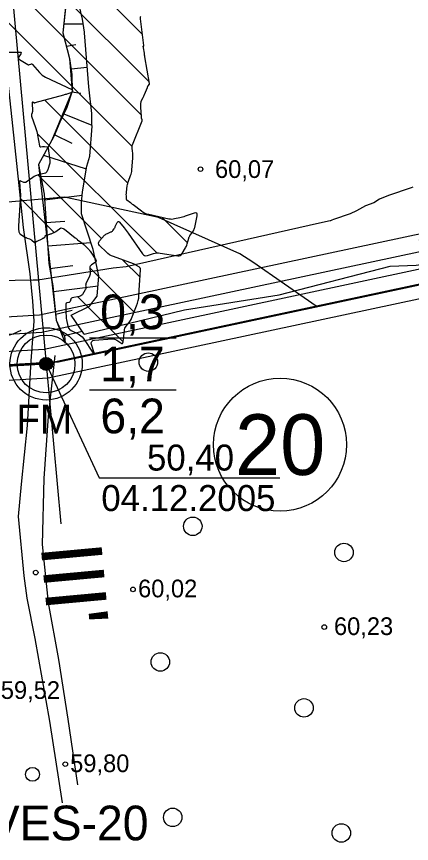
# Model space of a CAD drawing. Extents: x 532503 to 539665, y 6557663 to 6561526.
# Drawn here: x 534729.4 to 534784.1, y 6559418.8 to 6559533.2 of the extents above; entities that cross this region are included whole.
import ezdxf

# ---------------------------------------------------------------- set-up
doc = ezdxf.new("R2010")
doc.units = 0
for name, color, linetype in [('GEOLPUNKT', 7, 'Continuous'), ('HALJASTUS', 7, 'Continuous'), ('HORISONTAAL-EH2000', 7, 'Continuous'), ('illumineerimisjooned', 7, 'Continuous'), ('Kaevandatud ala', 7, 'Continuous'), ('kataster', 7, 'Continuous'), ('KORGUS-EH2000', 7, 'Continuous'), ('Lamami horisontaal_EH2000', 7, 'Continuous'), ('Lõige', 7, 'Continuous'), ('PIIR', 7, 'Continuous'), ('PIIR_me', 7, 'Continuous'), ('Plokid', 7, 'Continuous'), ('Proovid', 7, 'Continuous'), ('RELJEEF', 7, 'Continuous'), ('TEE', 7, 'Continuous'), ('TM_aktiivne', 7, 'Continuous'), ('Veetase', 7, 'Continuous')]:
    doc.layers.add(name, color=color, linetype=linetype)

# ---------------------------------------------------------------- blocks, each defined once
blk = doc.blocks.new('METS')
at = {"layer": 'HALJASTUS'}
blk.add_circle((0, 0), 0.8, dxfattribs=at)
blk = doc.blocks.new('LONOOR')
at = {"layer": 'HALJASTUS'}
blk.add_circle((0, 0), 0.6, dxfattribs=at)

msp = doc.modelspace()

# ---------------------------------------------------------------- linework, layer by layer
at = {"layer": 'GEOLPUNKT'}
for p, q in [((534739.5, 6559488.74), (534751.5, 6559488.74)), ((534739.5, 6559481.54), (534751.5, 6559481.54))]:
    msp.add_line(p, q, dxfattribs=at)
for radius in [5, 4, 0.9, 0.801, 0.7, 0.6, 0.5, 0.4, 0.3, 0.2, 0.1]:
    msp.add_circle((534733.5, 6559485.14), radius, dxfattribs=at)
at = {"layer": 'HORISONTAAL-EH2000'}
msp.add_lwpolyline([(534665.89, 6559465.57), (534680.27, 6559469.25), (534695.13, 6559472.57), (534702.12, 6559475.18), (534705.46, 6559476.87), (534710.19, 6559479.95), (534716.29, 6559484.76), (534719.55, 6559486.64), (534728.96, 6559489.29), (534730.07, 6559489.8)], dxfattribs=at)
at = {"layer": 'illumineerimisjooned'}
msp.add_lwpolyline([(534195.15, 6559981.19), (534198.98, 6559981.55), (535160.12, 6560071.77), (535418.53, 6559993.82), (535458.87, 6559929.25), (535494.63, 6559867.7), (535482.6, 6559826), (535251.74, 6559649.68), (535250.36, 6559648.53), (535180.45, 6559687.33), (534941.15, 6559814.59), (534876.93, 6559774.72), (534959.62, 6559531.32), (534733.77, 6559483.15), (534375.91, 6559461.87), (534195.51, 6559444.47)], dxfattribs=at)
msp.add_lwpolyline([(534967.67, 6560049.69), (534974.15, 6559828.08), (535058.69, 6559883.05), (535223.5, 6560002.45), (535218.56, 6560049.92), (535415.93, 6559990.42), (535455.45, 6559927.19), (535490.31, 6559867.16), (535479.12, 6559828.38), (535249.57, 6559653.05), (535182.36, 6559690.84), (534940.99, 6559819.22), (534872.14, 6559776.44), (534954.37, 6559534.34), (534950.91, 6559533.67), (534733.22, 6559487.12), (534375.58, 6559465.86), (534199.95, 6559448.92), (533951.79, 6559660.13), (534200.21, 6559977.65), (534931.63, 6560046.31)], close=True, dxfattribs=at)
at = {"layer": 'Kaevandatud ala'}
for p, q in [((534725.57, 6559552.02), (534746.84, 6559530.75)), ((534724.38, 6559547.55), (534747.78, 6559524.16)), ((534723.24, 6559543.04), (534746.68, 6559519.6)), ((534723.34, 6559537.28), (534745.4, 6559515.22)), ((534733.33, 6559521.64), (534744.81, 6559510.15)), ((534732.27, 6559517.03), (534748.81, 6559500.5)), ((534732.36, 6559511.29), (534741.17, 6559502.48)), ((534729.91, 6559508.08), (534734.64, 6559503.35)), ((534749.56, 6559505.4), (534753.07, 6559501.9)), ((534744.14, 6559499.51), (534746.52, 6559497.13)), ((534739.56, 6559498.43), (534745.68, 6559492.31)), ((534737.91, 6559494.43), (534744.16, 6559488.18)), ((534736.64, 6559490.04), (534736.8, 6559489.88)), ((534739.95, 6559486.73), (534740.13, 6559486.55)), ((534740.08, 6559486.54), (534740.21, 6559486.57))]:
    msp.add_line(p, q, dxfattribs=at)
for points in [[(534740.21, 6559486.57), (534740.17, 6559486.68), (534739.8, 6559487.82), (534739.76, 6559488.07), (534739.81, 6559488.25), (534739.96, 6559488.37), (534740.21, 6559488.43), (534742.65, 6559488.62), (534742.82, 6559488.62), (534742.98, 6559488.59), (534743.13, 6559488.54), (534743.28, 6559488.45), (534743.84, 6559488.05), (534743.97, 6559487.98), (534744.06, 6559487.98), (534744.13, 6559488.05), (534744.16, 6559488.19), (534744.34, 6559489.76), (534744.37, 6559489.92), (534744.42, 6559490.08), (534744.5, 6559490.22), (534744.59, 6559490.35), (534745.01, 6559490.87), (534745.11, 6559491.01), (534745.2, 6559491.15), (534745.27, 6559491.29), (534745.34, 6559491.44), (534746.03, 6559493.2), (534746.15, 6559493.54), (534746.25, 6559493.9), (534746.32, 6559494.26), (534746.35, 6559494.62), (534746.59, 6559498.18), (534746.58, 6559498.29), (534746.55, 6559498.38), (534746.49, 6559498.46), (534746.41, 6559498.53), (534746.01, 6559498.78), (534745.91, 6559498.84), (534745.81, 6559498.89), (534745.71, 6559498.94), (534745.6, 6559498.98), (534742.81, 6559499.99), (534742.54, 6559500.1), (534742.29, 6559500.24), (534742.06, 6559500.41), (534741.84, 6559500.6), (534740.9, 6559501.54), (534740.79, 6559501.69), (534740.75, 6559501.85), (534740.78, 6559502), (534740.89, 6559502.16), (534741.6, 6559502.95), (534741.69, 6559503.03), (534741.78, 6559503.1), (534741.87, 6559503.16), (534741.98, 6559503.21), (534742.48, 6559503.4), (534742.56, 6559503.43), (534742.62, 6559503.47), (534742.68, 6559503.53), (534742.73, 6559503.59), (534742.91, 6559503.86), (534742.95, 6559503.92), (534743, 6559503.99), (534743.04, 6559504.06), (534743.07, 6559504.14), (534743.35, 6559504.72), (534743.42, 6559504.81), (534743.49, 6559504.85), (534743.56, 6559504.83), (534743.65, 6559504.75), (534744.32, 6559503.96), (534744.46, 6559503.79), (534744.59, 6559503.62), (534744.73, 6559503.44), (534744.85, 6559503.26), (534746.83, 6559500.39), (534746.97, 6559500.23), (534747.13, 6559500.14), (534747.31, 6559500.11), (534747.52, 6559500.15), (534748.39, 6559500.42), (534748.61, 6559500.47), (534748.83, 6559500.5), (534749.05, 6559500.5), (534749.27, 6559500.48), (534751.72, 6559500.12), (534751.9, 6559500.12), (534752.07, 6559500.16), (534752.21, 6559500.26), (534752.32, 6559500.41), (534752.78, 6559501.19), (534752.86, 6559501.32), (534752.92, 6559501.46), (534752.98, 6559501.6), (534753.02, 6559501.74), (534753.25, 6559502.53), (534753.27, 6559502.57), (534753.28, 6559502.62), (534753.3, 6559502.66), (534753.32, 6559502.7), (534753.39, 6559502.87), (534753.41, 6559502.91), (534753.43, 6559502.95), (534753.45, 6559502.99), (534753.48, 6559503.03), (534753.89, 6559503.58), (534753.96, 6559503.69), (534754.02, 6559503.8), (534754.06, 6559503.92), (534754.09, 6559504.04), (534754.4, 6559505.64), (534754.42, 6559505.87), (534754.35, 6559506.01), (534754.21, 6559506.06), (534753.98, 6559506.01), (534752.75, 6559505.57), (534752.57, 6559505.51), (534752.38, 6559505.45), (534752.2, 6559505.4), (534752.01, 6559505.36), (534751.26, 6559505.2), (534751.07, 6559505.16), (534750.89, 6559505.15), (534750.7, 6559505.16), (534750.51, 6559505.19), (534747.71, 6559505.8), (534747.44, 6559505.88), (534747.18, 6559505.98), (534746.94, 6559506.11), (534746.71, 6559506.26), (534745.54, 6559507.15), (534745.45, 6559507.22), (534745.36, 6559507.3), (534745.26, 6559507.37), (534745.17, 6559507.44), (534744.69, 6559507.82), (534744.66, 6559507.86), (534744.64, 6559507.89), (534744.62, 6559507.93), (534744.62, 6559507.97), (534744.61, 6559508.16), (534744.61, 6559508.2), (534744.61, 6559508.25), (534744.61, 6559508.29), (534744.61, 6559508.34), (534744.6, 6559508.65), (534744.61, 6559508.72), (534744.61, 6559508.79), (534744.61, 6559508.86), (534744.62, 6559508.92), (534744.74, 6559509.8), (534744.77, 6559509.96), (534744.81, 6559510.13), (534744.85, 6559510.29), (534744.91, 6559510.45), (534745.2, 6559511.22), (534745.27, 6559511.41), (534745.32, 6559511.59), (534745.35, 6559511.78), (534745.37, 6559511.97), (534745.51, 6559513.67), (534745.51, 6559513.79), (534745.52, 6559513.91), (534745.51, 6559514.03), (534745.5, 6559514.15), (534745.44, 6559514.74), (534745.43, 6559514.8), (534745.43, 6559514.86), (534745.42, 6559514.92), (534745.42, 6559514.98), (534745.4, 6559515.22), (534745.4, 6559515.28), (534745.41, 6559515.34), (534745.42, 6559515.4), (534745.44, 6559515.45), (534746.82, 6559518.79), (534746.82, 6559518.8), (534746.82, 6559518.81), (534746.82, 6559518.82), (534746.82, 6559518.83), (534746.8, 6559518.88), (534746.79, 6559518.89), (534746.79, 6559518.9), (534746.79, 6559518.92), (534746.78, 6559518.93), (534746.75, 6559519.05), (534746.74, 6559519.07), (534746.74, 6559519.1), (534746.73, 6559519.12), (534746.73, 6559519.14), (534746.71, 6559519.28), (534746.7, 6559519.32), (534746.7, 6559519.35), (534746.7, 6559519.38), (534746.69, 6559519.41), (534746.65, 6559519.94), (534746.65, 6559520.04), (534746.64, 6559520.14), (534746.64, 6559520.24), (534746.63, 6559520.34), (534746.62, 6559521.14), (534746.63, 6559521.26), (534746.65, 6559521.37), (534746.68, 6559521.48), (534746.72, 6559521.58), (534746.93, 6559522), (534746.98, 6559522.1), (534747.03, 6559522.21), (534747.08, 6559522.32), (534747.12, 6559522.42), (534747.52, 6559523.42), (534747.53, 6559523.44), (534747.54, 6559523.46), (534747.55, 6559523.47), (534747.56, 6559523.49), (534747.6, 6559523.56), (534747.61, 6559523.57), (534747.62, 6559523.59), (534747.63, 6559523.6), (534747.64, 6559523.62), (534747.78, 6559523.8), (534747.8, 6559523.83), (534747.81, 6559523.87), (534747.82, 6559523.91), (534747.81, 6559523.95), (534747.18, 6559527.62), (534747.16, 6559527.75), (534747.14, 6559527.87), (534747.12, 6559528), (534747.1, 6559528.13), (534747, 6559528.88), (534747, 6559528.89), (534747, 6559528.9), (534747, 6559528.9), (534747, 6559528.91), (534746.98, 6559528.94), (534746.97, 6559528.95), (534746.92, 6559529.06), (534746.91, 6559529.08), (534746.91, 6559529.09), (534746.92, 6559529.1), (534746.94, 6559529.11), (534747.01, 6559529.13), (534747.03, 6559529.14), (534747.04, 6559529.15), (534747.05, 6559529.17), (534747.05, 6559529.19), (534746.56, 6559532.92), (534746.56, 6559533), (534746.57, 6559533.08), (534746.59, 6559533.16), (534746.63, 6559533.23)], [(534727.82, 6559528.29), (534729.89, 6559528.29), (534730, 6559528.27), (534730.05, 6559528.23), (534730.06, 6559528.16), (534730.01, 6559528.07), (534729.73, 6559527.64), (534729.68, 6559527.53), (534729.68, 6559527.44), (534729.72, 6559527.36), (534729.81, 6559527.29), (534730.96, 6559526.58), (534731.02, 6559526.55), (534731.07, 6559526.54), (534731.13, 6559526.54), (534731.18, 6559526.56), (534731.41, 6559526.64), (534731.47, 6559526.65), (534731.52, 6559526.65), (534731.56, 6559526.63), (534731.61, 6559526.59), (534732.57, 6559525.46), (534732.76, 6559525.27), (534732.96, 6559525.1), (534733.17, 6559524.95), (534733.41, 6559524.82), (534737.05, 6559523.11), (534737.07, 6559523.1), (534737.08, 6559523.09), (534737.09, 6559523.08), (534737.09, 6559523.07), (534737.13, 6559523), (534737.13, 6559523), (534737.13, 6559522.99), (534737.14, 6559522.98), (534737.14, 6559522.97), (534737.14, 6559522.96), (534737.14, 6559522.92), (534737.14, 6559522.91), (534737.14, 6559522.9), (534737.14, 6559522.89), (534737.14, 6559522.88), (534737.12, 6559522.76), (534737.11, 6559522.74), (534737.1, 6559522.72), (534737.09, 6559522.71), (534737.07, 6559522.7), (534736.38, 6559522.49), (534736.26, 6559522.45), (534736.13, 6559522.42), (534736.01, 6559522.38), (534735.89, 6559522.35), (534731.96, 6559521.26), (534731.92, 6559521.25), (534731.88, 6559521.25), (534731.84, 6559521.26), (534731.81, 6559521.28), (534731.67, 6559521.36), (534731.63, 6559521.37), (534731.61, 6559521.37), (534731.6, 6559521.35), (534731.59, 6559521.32), (534731.6, 6559520.09), (534731.6, 6559520.03), (534731.59, 6559519.97), (534731.58, 6559519.92), (534731.57, 6559519.87), (534731.49, 6559519.65), (534731.48, 6559519.6), (534731.47, 6559519.54), (534731.48, 6559519.49), (534731.49, 6559519.43), (534732.04, 6559517.85), (534732.13, 6559517.59), (534732.2, 6559517.33), (534732.27, 6559517.07), (534732.32, 6559516.8), (534732.58, 6559515.32), (534732.6, 6559515.26), (534732.64, 6559515.22), (534732.68, 6559515.19), (534732.75, 6559515.19), (534733.02, 6559515.21), (534733.09, 6559515.21), (534733.16, 6559515.21), (534733.23, 6559515.21), (534733.3, 6559515.21), (534733.62, 6559515.18), (534733.69, 6559515.17), (534733.74, 6559515.14), (534733.77, 6559515.09), (534733.79, 6559515.02), (534734.01, 6559513.3), (534734.02, 6559513.17), (534734.01, 6559513.05), (534734, 6559512.93), (534733.97, 6559512.8), (534733.8, 6559512.19), (534733.79, 6559512.13), (534733.76, 6559512.07), (534733.74, 6559512.01), (534733.71, 6559511.95), (534733.6, 6559511.71), (534733.57, 6559511.66), (534733.53, 6559511.61), (534733.48, 6559511.58), (534733.42, 6559511.56), (534732.38, 6559511.29), (534732.19, 6559511.24), (534732.01, 6559511.16), (534731.83, 6559511.07), (534731.67, 6559510.96), (534730.76, 6559510.31), (534730.68, 6559510.26), (534730.59, 6559510.24), (534730.49, 6559510.24), (534730.4, 6559510.27), (534730.02, 6559510.45), (534729.93, 6559510.48), (534729.88, 6559510.47), (534729.84, 6559510.42), (534729.84, 6559510.33), (534729.91, 6559509.03), (534729.92, 6559508.99), (534729.92, 6559508.95), (534729.92, 6559508.91), (534729.92, 6559508.87), (534729.94, 6559508.71), (534729.94, 6559508.67), (534729.94, 6559508.63), (534729.94, 6559508.59), (534729.94, 6559508.55), (534729.66, 6559504.23), (534729.66, 6559504.13), (534729.66, 6559504.03), (534729.66, 6559503.93), (534729.68, 6559503.82), (534729.73, 6559503.42), (534729.76, 6559503.32), (534729.8, 6559503.24), (534729.86, 6559503.16), (534729.94, 6559503.1), (534730.57, 6559502.7), (534730.64, 6559502.66), (534730.72, 6559502.62), (534730.8, 6559502.58), (534730.88, 6559502.55), (534731.22, 6559502.44), (534731.3, 6559502.41), (534731.37, 6559502.37), (534731.45, 6559502.32), (534731.52, 6559502.27), (534731.9, 6559501.96), (534731.93, 6559501.94), (534731.96, 6559501.93), (534731.98, 6559501.94), (534732.01, 6559501.96), (534732.13, 6559502.06), (534732.16, 6559502.09), (534732.19, 6559502.11), (534732.22, 6559502.13), (534732.25, 6559502.15), (534732.94, 6559502.46), (534732.98, 6559502.48), (534733.02, 6559502.51), (534733.06, 6559502.53), (534733.1, 6559502.55), (534733.33, 6559502.7), (534733.34, 6559502.71), (534733.34, 6559502.71), (534733.35, 6559502.72), (534733.36, 6559502.72), (534733.36, 6559502.73), (534733.37, 6559502.74), (534733.38, 6559502.75), (534733.38, 6559502.76), (534733.38, 6559502.77), (534733.4, 6559502.89), (534733.41, 6559502.91), (534733.42, 6559502.92), (534733.43, 6559502.94), (534733.45, 6559502.94), (534733.88, 6559503.06), (534733.95, 6559503.08), (534734.03, 6559503.1), (534734.1, 6559503.13), (534734.18, 6559503.16), (534734.55, 6559503.31), (534734.63, 6559503.35), (534734.72, 6559503.39), (534734.8, 6559503.44), (534734.87, 6559503.49), (534735.55, 6559503.99), (534735.55, 6559503.99), (534735.55, 6559503.99), (534735.56, 6559503.99), (534735.56, 6559503.99), (534735.86, 6559503.88), (534735.91, 6559503.86), (534735.95, 6559503.84), (534735.99, 6559503.81), (534736.03, 6559503.79), (534737.51, 6559502.6), (534737.6, 6559502.53), (534737.69, 6559502.46), (534737.78, 6559502.39), (534737.87, 6559502.32), (534738.31, 6559501.98), (534738.35, 6559501.95), (534738.4, 6559501.91), (534738.44, 6559501.88), (534738.48, 6559501.85), (534738.66, 6559501.72), (534738.7, 6559501.68), (534738.74, 6559501.65), (534738.78, 6559501.61), (534738.82, 6559501.57), (534739.28, 6559501.12), (534739.36, 6559501.03), (534739.44, 6559500.94), (534739.52, 6559500.84), (534739.59, 6559500.74), (534740.37, 6559499.57), (534740.43, 6559499.45), (534740.43, 6559499.35), (534740.39, 6559499.25), (534740.29, 6559499.17), (534739.79, 6559498.87), (534739.68, 6559498.78), (534739.6, 6559498.68), (534739.57, 6559498.56), (534739.56, 6559498.42), (534739.62, 6559497.84), (534739.62, 6559497.7), (534739.6, 6559497.56), (534739.57, 6559497.42), (534739.52, 6559497.29), (534739.02, 6559496.23), (534739, 6559496.16), (534738.98, 6559496.09), (534738.97, 6559496.02), (534738.98, 6559495.95), (534739, 6559495.66), (534739, 6559495.59), (534738.99, 6559495.52), (534738.96, 6559495.45), (534738.93, 6559495.39), (534738.52, 6559494.77), (534738.44, 6559494.65), (534738.33, 6559494.56), (534738.21, 6559494.5), (534738.07, 6559494.46), (534737.1, 6559494.27), (534737.03, 6559494.25), (534736.98, 6559494.21), (534736.94, 6559494.16), (534736.91, 6559494.09), (534736.82, 6559493.79), (534736.79, 6559493.73), (534736.75, 6559493.68), (534736.71, 6559493.65), (534736.64, 6559493.63), (534736.38, 6559493.58), (534736.32, 6559493.56), (534736.28, 6559493.53), (534736.25, 6559493.48), (534736.25, 6559493.42), (534736.25, 6559492.09), (534736.26, 6559491.87), (534736.27, 6559491.66), (534736.3, 6559491.45), (534736.33, 6559491.23), (534736.49, 6559490.39), (534736.55, 6559490.19), (534736.65, 6559490.03), (534736.78, 6559489.89), (534736.96, 6559489.78), (534737.93, 6559489.31), (534738.14, 6559489.19), (534738.33, 6559489.04), (534738.51, 6559488.87), (534738.66, 6559488.67), (534740.03, 6559486.61), (534740.08, 6559486.54)]]:
    msp.add_lwpolyline(points, dxfattribs=at)
at = {"layer": 'kataster'}
msp.add_lwpolyline([(533947.7, 6559658.95), (533949.2, 6559955.8), (534198.28, 6559979.48), (535159.89, 6560069.73), (535417.31, 6559992.13), (535457.22, 6559928.24), (535504.86, 6559846.09), (535250.3, 6559650.84), (535181.52, 6559689.04), (534941.15, 6559817.08), (534874.65, 6559775.26), (534957.01, 6559532.73), (534735.22, 6559485.45), (534375.71, 6559463.85), (534199.28, 6559446.9), (534122.84, 6559439.44), (534110.45, 6559447.36), (534092.53, 6559453.94), (534085.13, 6559454.75)], close=True, dxfattribs=at)
msp.add_lwpolyline([(534375.71, 6559463.85), (534735.22, 6559485.45), (534957.01, 6559532.73), (534969.93, 6559494.75), (535054.28, 6559206.76), (535041.77, 6559209.47), (535017.76, 6559212.2), (534998.41, 6559211.16), (534957.01, 6559202.5), (534925.72, 6559202.71), (534804.31, 6559232.52), (534740.37, 6559246.64), (534719.3, 6559250.08), (534702.52, 6559249.07), (534633.14, 6559232.3)], dxfattribs=at)
at = {"layer": 'KORGUS-EH2000'}
for centre in [(534754.88, 6559512.1), (534732.06, 6559456.27), (534745.53, 6559453.94), (534772.01, 6559448.72), (534736.16, 6559429.75)]:
    msp.add_circle(centre, 0.32, dxfattribs=at)
at = {"layer": 'Lamami horisontaal_EH2000'}
msp.add_lwpolyline([(534770.89, 6559493.12), (534762.11, 6559499.23), (534760.3, 6559500.36), (534749.08, 6559505.42), (534736.04, 6559508.23), (534723.01, 6559507.05), (534709.98, 6559502.01), (534706.98, 6559500.36), (534696.94, 6559492.56), (534691.02, 6559487.46), (534686.71, 6559482.36)], dxfattribs=at)
at = {"layer": 'Lõige'}
msp.add_lwpolyline([(534686.42, 6560054.5), (534688.17, 6560025.47), (534697.52, 6559887.98), (534707.91, 6559763.06), (534733.5, 6559485.14), (534735.54, 6559463.02)], dxfattribs=at)
at = {"layer": 'PIIR'}
for centre, radius in [((534733.49, 6559485.13), 0.88), ((534733.49, 6559485.13), 0.88), ((534733.49, 6559485.13), 0.88), ((534765.89, 6559473.97), 9.2)]:
    msp.add_circle(centre, radius, dxfattribs=at)
at = {"layer": 'PIIR_me'}
msp.add_lwpolyline([(534441.63, 6560002.32), (534688.17, 6560025.46), (534931.44, 6560048.3), (534969.61, 6560051.88), (534976.05, 6559831.7), (535057.56, 6559884.7), (535221.39, 6560003.39), (535216.26, 6560052.7), (535417.23, 6559992.12), (535457.16, 6559928.22), (535492.47, 6559867.43), (535480.86, 6559827.19), (535250.12, 6559650.95), (535250.12, 6559650.95), (535181.4, 6559689.09), (534941.07, 6559816.91), (534874.54, 6559775.58), (534957, 6559532.81), (534951.31, 6559531.71), (534733.49, 6559485.13), (534485.11, 6559470.37)], dxfattribs=at)
at = {"layer": 'Plokid'}
for points in [[(534951.24, 6559536.08), (534732.91, 6559489.51), (534375.41, 6559468.25), (534200.75, 6559451.41), (533955.1, 6559660.46), (534201.47, 6559975.36), (534969.74, 6560047.47)], [(534950.46, 6559538.37), (534732.58, 6559491.9), (534375.22, 6559470.64), (534201.53, 6559453.89), (533958.41, 6559660.8), (534202.72, 6559973.06), (534969.81, 6560045.07)], [(534784.29, 6559509.61), (534784.04, 6559509.52), (534780.91, 6559508.43), (534779.66, 6559507.96), (534778.87, 6559507.44), (534777.72, 6559507), (534776.45, 6559506.35), (534775.61, 6559505.9), (534773.3, 6559505.13), (534773.06, 6559505.02), (534772.85, 6559504.94), (534772.84, 6559504.94), (534771.35, 6559504.6), (534744.6, 6559498.58), (534742.79, 6559498.41), (534732.37, 6559496.74), (534731.73, 6559496.74), (534721.63, 6559496.54)]]:
    msp.add_lwpolyline(points, dxfattribs=at)
at = {"layer": 'RELJEEF'}
for p, q in [((534735.95, 6559532.21), (534738.64, 6559532.23)), ((534737.62, 6559529.3), (534736.31, 6559529.09)), ((534736.95, 6559525.96), (534739.2, 6559526.22)), ((534738.3, 6559522.58), (534737.05, 6559522.77)), ((534735.97, 6559519.77), (534739.83, 6559518.2)), ((534737.13, 6559515.64), (534734.65, 6559516.85)), ((534733.16, 6559514.02), (534739.07, 6559512.14)), ((534735.84, 6559511.07), (534732.77, 6559511.03)), ((534733.27, 6559507.87), (534738.5, 6559508.48)), ((534736.09, 6559504.86), (534733.51, 6559504.68)), ((534733.73, 6559501.49), (534739.68, 6559501.96)), ((534737.21, 6559498.71), (534734.02, 6559498.3)), ((534734.53, 6559495.15), (534740.69, 6559495.94)), ((534737.13, 6559492.53), (534734.83, 6559491.96)), ((534736.03, 6559489.06), (534738.51, 6559489.66))]:
    msp.add_line(p, q, dxfattribs=at)
for points in [[(534717.46, 6559649.15), (534716.71, 6559646.22), (534718.13, 6559632.61), (534719.8, 6559612.72), (534721.63, 6559596.85), (534722.62, 6559589.56), (534723.51, 6559574.93), (534724.82, 6559559.33), (534726.06, 6559547.78), (534727.26, 6559534.66), (534727.8, 6559527.98), (534728.74, 6559518.98), (534729.8, 6559508.95), (534730.34, 6559504.03), (534731.25, 6559497.63), (534731.61, 6559493.84), (534731.79, 6559491.07)], [(534736.62, 6559538.58), (534736.27, 6559535.26), (534735.82, 6559530.94), (534736.76, 6559527.42), (534737.05, 6559525.21), (534737.09, 6559522.9), (534736.37, 6559520.61), (534735.42, 6559518.6), (534734.56, 6559516.63), (534732.46, 6559512.73), (534733.21, 6559508.64), (534733.61, 6559503.29), (534733.88, 6559499.03), (534734.45, 6559495.96), (534734.91, 6559491.21), (534735.25, 6559490.38), (534735.72, 6559489.43), (534736.06, 6559489.02), (534736.14, 6559488)], [(534736.62, 6559538.58), (534735.82, 6559530.94), (534736.76, 6559527.42), (534737.09, 6559522.9), (534734.29, 6559516.13), (534732.46, 6559512.73), (534734.91, 6559491.21), (534736.14, 6559488)], [(534738.77, 6559489.28), (534736.99, 6559491.9), (534739.52, 6559493.15), (534740.58, 6559494.54), (534740.8, 6559497.31), (534740, 6559500.98), (534738.4, 6559505.91), (534738.42, 6559507.42), (534738.54, 6559508.98), (534739.13, 6559512.49), (534739.56, 6559513.91), (534739.88, 6559518.03), (534739.83, 6559518.17), (534739.84, 6559519.82), (534739.41, 6559523.48), (534738.82, 6559530.96), (534738.81, 6559531.06), (534738.55, 6559532.85), (534738.13, 6559534.59), (534736.62, 6559538.58)], [(534738.77, 6559489.28), (534752.65, 6559492.62), (534765.78, 6559494.72), (534781.11, 6559498.66), (534784.74, 6559498.8), (534786.08, 6559499), (534785.18, 6559502.32), (534788.91, 6559503.46), (534789.21, 6559503.75), (534790.98, 6559507.75), (534795.8, 6559507.45), (534800.7, 6559507.25), (534806, 6559508.51), (534812.87, 6559506.07), (534818.85, 6559505.71), (534825.23, 6559507.52), (534832.58, 6559509), (534839.76, 6559510.48), (534846.17, 6559513.26), (534856.37, 6559513.85), (534869.49, 6559514.84)]]:
    msp.add_lwpolyline(points, dxfattribs=at)
at = {"layer": 'TEE'}
for points in [[(534731.79, 6559491.07), (534731.37, 6559485.55), (534730.87, 6559476.6), (534730.05, 6559468.49), (534729.64, 6559464.04), (534730.44, 6559455.83), (534730.85, 6559452.73), (534731.94, 6559447.16), (534733.95, 6559435.68), (534735.71, 6559424.38)], [(534734.69, 6559486.33), (534733.8, 6559477.93), (534733.19, 6559469.3), (534732.97, 6559460.17), (534733.79, 6559452.06), (534735.22, 6559444.22), (534736.51, 6559435.98), (534737.87, 6559426.91)]]:
    msp.add_lwpolyline(points, dxfattribs=at)
at = {"layer": 'TM_aktiivne'}
msp.add_lwpolyline([(535159.92, 6560069.74), (535417.23, 6559992.12), (535457.16, 6559928.22), (535492.47, 6559867.43), (535480.86, 6559827.19), (535250.49, 6559651.24), (535250.13, 6559650.94), (535181.4, 6559689.09), (534941.07, 6559816.9), (534874.53, 6559775.58), (534957, 6559532.81), (534733.5, 6559485.14), (534375.75, 6559463.86), (534199.32, 6559446.85), (534124.95, 6559439.68), (533949.03, 6559659.85), (533949.15, 6559955.79), (534199.17, 6559979.56)], close=True, dxfattribs=at)
at = {"layer": 'Veetase'}
for p, q in [((534733.5, 6559485.14), (534740.84, 6559469.38)), ((534740.84, 6559469.38), (534765.84, 6559469.38))]:
    msp.add_line(p, q, dxfattribs=at)

# ---------------------------------------------------------------- block references
at = {"layer": 'HALJASTUS', "xscale": 1.6, "yscale": 1.6000000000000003}
for name, p in [('METS', (534747.66, 6559485.39)), ('METS', (534753.81, 6559462.67)), ('METS', (534774.74, 6559459.05)), ('METS', (534749.31, 6559443.89)), ('METS', (534769.2, 6559437.54)), ('LONOOR', (534731.62, 6559428.34)), ('METS', (534751.03, 6559422.39)), ('METS', (534774.37, 6559420.23))]:
    msp.add_blockref(name, p, dxfattribs=at)

# ---------------------------------------------------------------- texts
at = {"layer": 'GEOLPUNKT'}
for s, p in [('0,3', (534740.99, 6559489.94)), ('1,7', (534740.99, 6559482.74)), ('6,2', (534741.02, 6559475.54)), ('VES-20', (534725.56, 6559419.21))]:
    msp.add_text(s, height=4.8, dxfattribs=at).set_placement(p)
at = {"layer": 'KORGUS-EH2000'}
for s, p in [('60,07 ', (534756.88, 6559510.88)), ('60,02', (534746.23, 6559452.84)), ('60,23', (534773.35, 6559447.62)), ('59,52', (534727.23, 6559438.78)), ('59,80', (534736.83, 6559428.65))]:
    msp.add_text(s, height=2.45, dxfattribs=at).set_placement(p)
at = {"layer": 'Lõige'}
msp.add_text("III'", height=8.4, rotation=275.2608, dxfattribs=at).set_placement((534732.74, 6559460.03))
at = {"layer": 'PIIR'}
msp.add_text('20', height=8.4, dxfattribs=at).set_placement((534759.66, 6559469.77))
at = {"layer": 'Proovid'}
msp.add_text('FM', height=4, dxfattribs=at).set_placement((534729.38, 6559475.5))
at = {"layer": 'Veetase'}
for s, p in [('50,40', (534747.47, 6559470.38)), ('04.12.2005', (534741.15, 6559464.78))]:
    msp.add_text(s, height=3.6, dxfattribs=at).set_placement(p)

doc.saveas('drawing.dxf')
